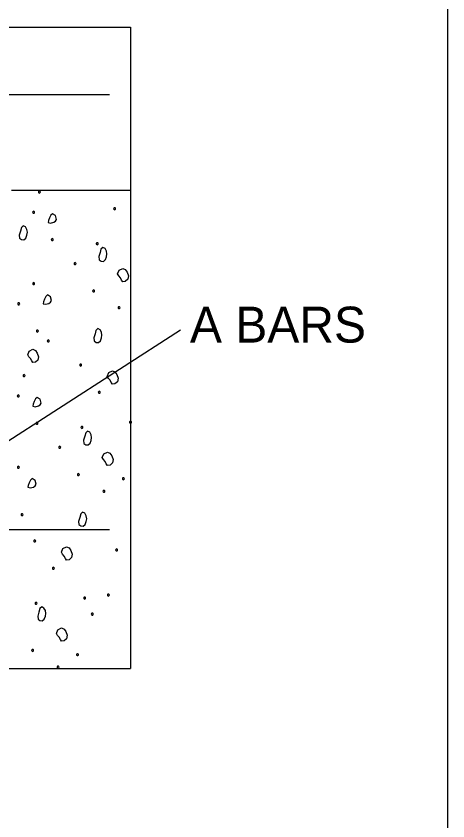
# Model space of a CAD drawing. Extents: x -439.2 to -407.9, y -458.1 to -436.2.
# Drawn here: x -409.689 to -407.859, y -445.233 to -441.825 of the extents above; entities that cross this region are included whole.
import ezdxf

# ---------------------------------------------------------------- set-up
doc = ezdxf.new("R2010")
doc.units = 0
doc.layers.add('Bridge-Named Boundary', color=7, linetype='Continuous')
doc.layers.add('Level 4', color=7, linetype='Continuous')

msp = doc.modelspace()

# ---------------------------------------------------------------- linework, layer by layer
at = {"layer": 'Bridge-Named Boundary'}
msp.add_lwpolyline([(-439.109, -458.0508), (-407.859, -458.0508), (-407.859, -437.6758), (-439.109, -437.6758)], close=True, dxfattribs=at)
at = {"layer": 'Level 4'}
for p, q in [((-413.7894, -441.872), (-409.204, -441.872)), ((-409.204, -441.872), (-409.204, -444.5887)), ((-413.7001, -442.1574), (-409.2933, -442.1574)), ((-409.7091, -442.5621), (-409.204, -442.5621)), ((-409.8094, -443.6798), (-408.9924, -443.1544)), ((-413.676, -443.9998), (-409.2933, -443.9998)), ((-413.7894, -444.5887), (-409.204, -444.5887))]:
    msp.add_line(p, q, dxfattribs=at)
for points in [[(-409.535, -442.6625), (-409.5428, -442.6685), (-409.548, -442.6796), (-409.5527, -442.691), (-409.5532, -442.6994), (-409.5437, -442.7018), (-409.5298, -442.6981), (-409.522, -442.6933), (-409.5181, -442.6862), (-409.5224, -442.6701), (-409.535, -442.6625)], [(-409.6588, -442.7134), (-409.6667, -442.7209), (-409.6705, -442.7357), (-409.6758, -442.7528), (-409.6744, -442.766), (-409.6662, -442.7717), (-409.6562, -442.7726), (-409.6478, -442.7651), (-409.6432, -442.7528), (-409.6414, -442.7409), (-409.6432, -442.7292), (-409.6492, -442.7182), (-409.6588, -442.7134)], [(-409.3218, -442.8046), (-409.3297, -442.8122), (-409.3335, -442.827), (-409.3388, -442.844), (-409.3373, -442.8573), (-409.3292, -442.863), (-409.3192, -442.8639), (-409.3107, -442.8564), (-409.3062, -442.8441), (-409.3044, -442.8322), (-409.3062, -442.8204), (-409.3122, -442.8095), (-409.3218, -442.8046)], [(-409.2592, -442.9173), (-409.2527, -442.9014), (-409.2372, -442.8936), (-409.2269, -442.8985), (-409.219, -442.9094), (-409.2133, -442.9249), (-409.2164, -442.9397), (-409.2264, -442.9487), (-409.2372, -442.9502), (-409.2426, -442.9431), (-409.2475, -442.9331), (-409.2546, -442.9254), (-409.2592, -442.9173)], [(-409.556, -443.0063), (-409.5638, -443.0123), (-409.569, -443.0234), (-409.5738, -443.0348), (-409.5742, -443.0432), (-409.5647, -443.0456), (-409.5509, -443.0419), (-409.5431, -443.037), (-409.5392, -443.03), (-409.5434, -443.0139), (-409.556, -443.0063)], [(-409.3428, -443.1484), (-409.3508, -443.156), (-409.3545, -443.1708), (-409.3598, -443.1878), (-409.3584, -443.2011), (-409.3502, -443.2068), (-409.3402, -443.2077), (-409.3318, -443.2002), (-409.3273, -443.1879), (-409.3254, -443.176), (-409.3273, -443.1642), (-409.3333, -443.1533), (-409.3428, -443.1484)], [(-409.64, -443.2599), (-409.6334, -443.2439), (-409.6179, -443.2362), (-409.6076, -443.2411), (-409.5998, -443.252), (-409.5941, -443.2675), (-409.5972, -443.2823), (-409.6072, -443.2912), (-409.6179, -443.2928), (-409.6234, -443.2856), (-409.6283, -443.2757), (-409.6353, -443.268), (-409.64, -443.2599)], [(-409.303, -443.3512), (-409.2964, -443.3352), (-409.2809, -443.3275), (-409.2706, -443.3324), (-409.2627, -443.3433), (-409.257, -443.3587), (-409.2601, -443.3736), (-409.2702, -443.3825), (-409.2809, -443.3841), (-409.2863, -443.3769), (-409.2913, -443.367), (-409.2983, -443.3593), (-409.303, -443.3512)], [(-409.5998, -443.4402), (-409.6076, -443.4462), (-409.6128, -443.4573), (-409.6175, -443.4687), (-409.6179, -443.477), (-409.6085, -443.4794), (-409.5946, -443.4757), (-409.5868, -443.4709), (-409.5829, -443.4639), (-409.5871, -443.4477), (-409.5998, -443.4402)], [(-409.3866, -443.5823), (-409.3945, -443.5898), (-409.3982, -443.6047), (-409.4035, -443.6217), (-409.4021, -443.635), (-409.3939, -443.6406), (-409.384, -443.6415), (-409.3755, -443.634), (-409.371, -443.6218), (-409.3692, -443.6099), (-409.371, -443.5981), (-409.377, -443.5871), (-409.3866, -443.5823)], [(-409.324, -443.695), (-409.3174, -443.679), (-409.302, -443.6713), (-409.2917, -443.6762), (-409.2838, -443.6871), (-409.2781, -443.7025), (-409.2812, -443.7173), (-409.2912, -443.7263), (-409.302, -443.7279), (-409.3074, -443.7207), (-409.3123, -443.7108), (-409.3193, -443.7031), (-409.324, -443.695)], [(-409.6208, -443.784), (-409.6286, -443.79), (-409.6338, -443.8011), (-409.6386, -443.8125), (-409.639, -443.8208), (-409.6295, -443.8232), (-409.6156, -443.8195), (-409.6079, -443.8147), (-409.604, -443.8077), (-409.6082, -443.7915), (-409.6208, -443.784)], [(-409.4076, -443.9261), (-409.4156, -443.9336), (-409.4193, -443.9485), (-409.4246, -443.9655), (-409.4232, -443.9787), (-409.415, -443.9844), (-409.405, -443.9853), (-409.3966, -443.9778), (-409.3921, -443.9656), (-409.3902, -443.9537), (-409.3921, -443.9419), (-409.3981, -443.9309), (-409.4076, -443.9261)], [(-409.4973, -444.096), (-409.4908, -444.08), (-409.4753, -444.0723), (-409.465, -444.0772), (-409.4571, -444.0881), (-409.4514, -444.1035), (-409.4545, -444.1183), (-409.4645, -444.1273), (-409.4753, -444.1289), (-409.4807, -444.1217), (-409.4856, -444.1118), (-409.4927, -444.1041), (-409.4973, -444.096)], [(-409.5809, -444.3271), (-409.5889, -444.3346), (-409.5926, -444.3495), (-409.5979, -444.3665), (-409.5965, -444.3797), (-409.5883, -444.3854), (-409.5783, -444.3863), (-409.5699, -444.3788), (-409.5654, -444.3666), (-409.5635, -444.3547), (-409.5654, -444.3429), (-409.5714, -444.3319), (-409.5809, -444.3271)], [(-409.5184, -444.4397), (-409.5118, -444.4238), (-409.4963, -444.4161), (-409.486, -444.421), (-409.4782, -444.4318), (-409.4725, -444.4473), (-409.4756, -444.4621), (-409.4856, -444.4711), (-409.4963, -444.4727), (-409.5018, -444.4655), (-409.5067, -444.4555), (-409.5137, -444.4479), (-409.5184, -444.4397)]]:
    msp.add_lwpolyline(points, close=True, dxfattribs=at)
for centre, start_param, end_param in [((-409.5908, -442.5703), 4.712389, 7.853982), ((-409.5908, -442.5703), 1.570796, 4.712389), ((-409.6154, -442.656), 4.712389, 7.853982), ((-409.272, -442.6408), 4.712389, 7.853982), ((-409.272, -442.6408), 1.570796, 4.712389), ((-409.6154, -442.656), 1.570796, 4.712389), ((-409.5364, -442.7717), 4.712389, 7.853982), ((-409.5364, -442.7717), 1.570796, 4.712389), ((-409.3457, -442.7895), 4.712389, 7.853982), ((-409.3457, -442.7895), 1.570796, 4.712389), ((-409.4396, -442.8736), 4.712389, 7.853982), ((-409.4396, -442.8736), 1.570796, 4.712389), ((-409.615, -442.9579), 4.712389, 7.853982), ((-409.615, -442.9579), 1.570796, 4.712389), ((-409.3607, -442.9892), 4.712389, 7.853982), ((-409.3607, -442.9892), 1.570796, 4.712389), ((-409.6783, -443.0437), 4.712389, 7.853982), ((-409.6783, -443.0437), 1.570796, 4.712389), ((-409.2526, -443.06), 4.712389, 7.853982), ((-409.2526, -443.06), 1.570796, 4.712389), ((-409.5993, -443.1593), 4.712389, 7.853982), ((-409.5993, -443.1593), 1.570796, 4.712389), ((-409.5529, -443.2009), 4.712389, 7.853982), ((-409.5529, -443.2009), 1.570796, 4.712389), ((-409.4157, -443.3028), 4.712389, 7.853982), ((-409.4157, -443.3028), 1.570796, 4.712389), ((-409.6556, -443.3479), 4.712389, 7.853982), ((-409.6556, -443.3479), 1.570796, 4.712389), ((-409.6802, -443.4337), 4.712389, 7.853982), ((-409.6802, -443.4337), 1.570796, 4.712389), ((-409.3368, -443.4185), 4.712389, 7.853982), ((-409.3368, -443.4185), 1.570796, 4.712389), ((-409.6012, -443.5493), 4.712389, 7.853982), ((-409.6012, -443.5493), 1.570796, 4.712389), ((-409.4105, -443.5671), 4.712389, 7.853982), ((-409.4105, -443.5671), 1.570796, 4.712389), ((-409.2045, -443.5449), 4.712389, 7.853982), ((-409.2045, -443.5449), 1.570796, 4.712389), ((-409.5044, -443.6512), 4.712389, 7.853982), ((-409.5044, -443.6512), 1.570796, 4.712389), ((-409.6798, -443.7356), 4.712389, 7.853982), ((-409.6798, -443.7356), 1.570796, 4.712389), ((-409.4255, -443.7669), 4.712389, 7.853982), ((-409.4255, -443.7669), 1.570796, 4.712389), ((-409.2347, -443.7846), 4.712389, 7.853982), ((-409.2347, -443.7846), 1.570796, 4.712389), ((-409.3173, -443.8377), 4.712389, 7.853982), ((-409.3173, -443.8377), 1.570796, 4.712389), ((-409.6641, -443.937), 4.712389, 7.853982), ((-409.6641, -443.937), 1.570796, 4.712389), ((-409.6101, -444.0476), 4.712389, 7.853982), ((-409.6101, -444.0476), 1.570796, 4.712389), ((-409.2632, -444.0859), 4.712389, 7.853982), ((-409.2632, -444.0859), 1.570796, 4.712389), ((-409.5311, -444.1633), 4.712389, 7.853982), ((-409.5311, -444.1633), 1.570796, 4.712389), ((-409.3988, -444.2897), 4.712389, 7.853982), ((-409.3988, -444.2897), 1.570796, 4.712389), ((-409.2982, -444.2771), 4.712389, 7.853982), ((-409.2982, -444.2771), 1.570796, 4.712389), ((-409.6048, -444.3119), 4.712389, 7.853982), ((-409.6048, -444.3119), 1.570796, 4.712389), ((-409.3664, -444.3579), 4.712389, 7.853982), ((-409.3664, -444.3579), 1.570796, 4.712389), ((-409.6198, -444.5116), 4.712389, 7.853982), ((-409.6198, -444.5116), 1.570796, 4.712389), ((-409.4291, -444.5294), 4.712389, 7.853982), ((-409.4291, -444.5294), 1.570796, 4.712389), ((-409.5117, -444.5824), 4.712389, 7.853982), ((-409.5117, -444.5824), 1.570796, 4.712389)]:
    msp.add_ellipse(centre, major_axis=(0, 0.00422), ratio=0.985935, start_param=start_param, end_param=end_param, dxfattribs=at)

# ---------------------------------------------------------------- texts
msp.add_text('A BARS', height=0.15214, dxfattribs=at).set_placement((-408.9525, -443.2079))

doc.saveas('drawing.dxf')
